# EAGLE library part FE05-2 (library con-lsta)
FEMALE HEADER
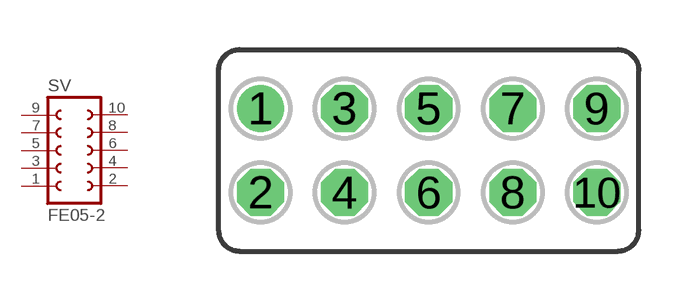
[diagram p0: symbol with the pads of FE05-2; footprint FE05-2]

Designator prefix SV

## FE05-2 (OC_FARNELL: unknown; OC_NEWARK: unknown)  [FE05-2]
1  1  pas
2  2  pas
3  3  pas
4  4  pas
5  5  pas
6  6  pas
7  7  pas
8  8  pas
9  9  pas
10  10  pas

## Footprint FE05-2 (pad centres in mm)
FEMALE HEADER
drill 0.914 round: 1 -5.08,1.27
drill 0.914 octagon: 2 -5.08,-1.27; 3 -2.54,1.27; 4 -2.54,-1.27; 5 0,1.27; 6 0,-1.27; 7 2.54,1.27; 8 2.54,-1.27; 9 5.08,1.27; 10 5.08,-1.27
